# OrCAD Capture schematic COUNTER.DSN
size A
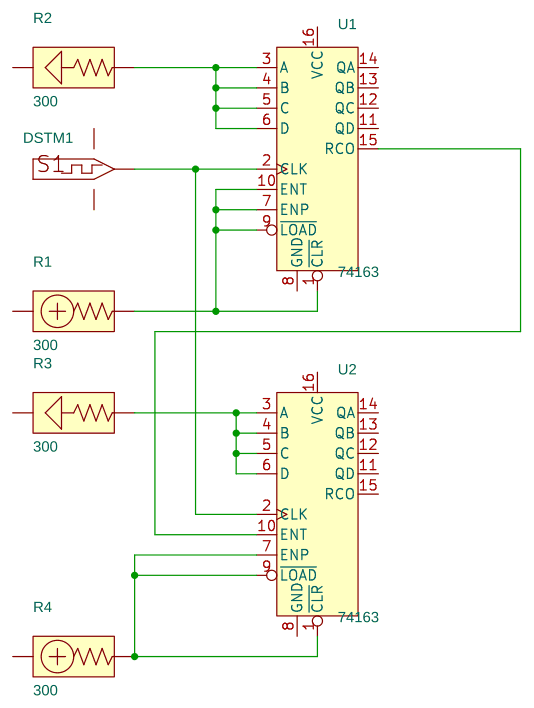
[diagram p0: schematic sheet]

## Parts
DSTM1  DigStim1
R1  300
R2  300
R3  300
R4  300
U1  74163  [DIP10016W300L900]
U2  74163  [DIP10016W300L900]

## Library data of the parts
DSTM1 = DigStim1
R1 R4 = PULLUP
R2 R3 = PULLDOWN
U1 U2 = 74163

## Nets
GND: DSTM1.3(GND) R2.2(GND) R3.2(GND) U1.8(GND) U2.8(GND)
VCC: DSTM1.2(VCC) R1.2(VCC) R4.2(VCC) U1.16(VCC) U2.16(VCC)
N00265: R2.1 U1.3(A) U1.4(B) U1.5(C) U1.6(D)
N00412: DSTM1.OUT U1.2(CLK) U2.2(CLK)
N00420: R1.1 U1.1(~{CLR}) U1.7(ENP) U1.9(~{LOAD}) U1.10(ENT)
N00460: U1.15(RCO) U2.10(ENT)
N00513: R3.1 U2.3(A) U2.4(B) U2.5(C) U2.6(D)
N00553: R4.1 U2.1(~{CLR}) U2.7(ENP) U2.9(~{LOAD})

Not connected (* = marked no-connect by the designer): U1 11(QD) 12(QC) 13(QB) 14(QA); U2 11(QD) 12(QC) 13(QB) 14(QA) 15(RCO)
